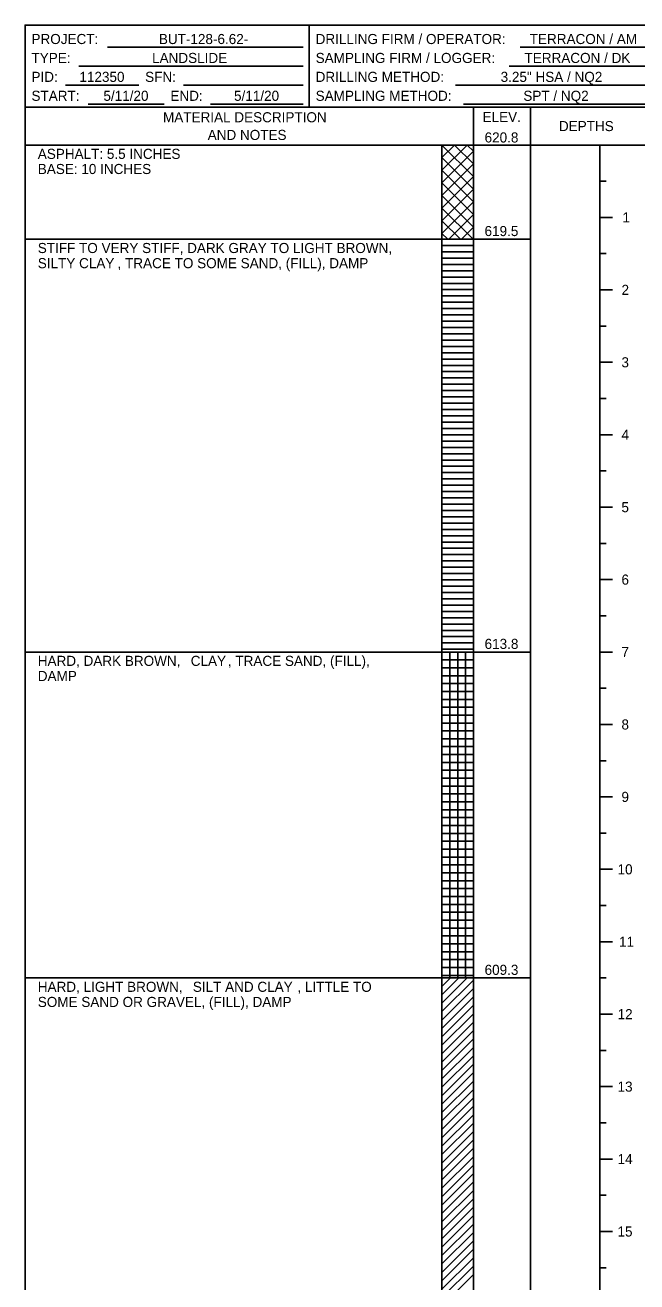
# Model space of a CAD drawing. Extents: x 0 to 0.83, y -0.65 to 1.27.
# Drawn here: x 0 to 0.404, y 0.445 to 1.275 of the extents above; entities that cross this region are included whole.
import ezdxf

# ---------------------------------------------------------------- set-up
doc = ezdxf.new("R2010")
doc.units = 0

msp = doc.modelspace()

# ---------------------------------------------------------------- linework, layer by layer
msp.add_lwpolyline([(0, 0), (0.83333, 0), (0.83333, 1.275), (0, 1.275)], close=True)
msp.add_lwpolyline([(0, 0), (0.83333, 0), (0.83333, 1.275), (0, 1.275)], close=True)
msp.add_lwpolyline([(0, 0), (0.83333, 0), (0.83333, 1.275), (0, 1.275)], close=True)
msp.add_lwpolyline([(0, 0), (0.83333, 0), (0.83333, 1.275), (0, 1.275)], close=True)
msp.add_lwpolyline([(0, 0), (0.83333, 0), (0.83333, 1.275), (0, 1.275)], close=True)
for points in [[(0.1875, 1.22083), (0.1875, 1.275)], [(0.05444, 1.26041), (0.18333, 1.26041)], [(0.32667, 1.26041), (0.4125, 1.26041)], [(0.03542, 1.24791), (0.18333, 1.24791)], [(0.31944, 1.24791), (0.4125, 1.24791)], [(0.02653, 1.23541), (0.075, 1.23541)], [(0.10458, 1.23541), (0.18333, 1.23541)], [(0.28403, 1.23541), (0.4125, 1.23541)], [(0, 1.22083), (0.83333, 1.22083)], [(0, 1.22083), (0.83333, 1.22083)], [(0, 1.22083), (0.83333, 1.22083)], [(0, 1.22083), (0.83333, 1.22083)], [(0, 1.22083), (0.83333, 1.22083)], [(0.04153, 1.22291), (0.09167, 1.22291)], [(0.12222, 1.22291), (0.18333, 1.22291)], [(0.2893, 1.22291), (0.4125, 1.22291)], [(0.29583, 1.22083), (0.29583, -0.64575)], [(0.29583, 1.22083), (0.29583, -0.64575)], [(0.33333, 1.22083), (0.33333, -0.64575)], [(0.33333, 1.22083), (0.33333, -0.64575)], [(0, 1.19583), (0.83333, 1.19583)], [(0, 1.19583), (0.83333, 1.19583)], [(0, 1.19583), (0.83333, 1.19583)], [(0, 1.19583), (0.83333, 1.19583)], [(0, 1.19583), (0.83333, 1.19583)], [(0.275, 1.19583), (0.29583, 1.175)], [(0.275, 1.1875), (0.28333, 1.19583)], [(0.275, 1.17916), (0.29167, 1.19583)], [(0.275, 1.19583), (0.275, 1.13365)], [(0.275, 1.19583), (0.275, -0.64575)], [(0.28333, 1.19583), (0.29583, 1.18333)], [(0.29167, 1.19583), (0.29583, 1.19166)], [(0.29583, 1.19583), (0.33333, 1.19583)], [(0.37917, 1.19583), (0.37917, -0.64575)], [(0.275, 1.17083), (0.29583, 1.19166)], [(0.275, 1.1875), (0.29583, 1.16666)], [(0.275, 1.1625), (0.29583, 1.18333)], [(0.275, 1.17916), (0.29583, 1.15833)], [(0.275, 1.15416), (0.29583, 1.175)], [(0.275, 1.17083), (0.29583, 1.15)], [(0.37917, 1.17191), (0.38333, 1.17191)], [(0.275, 1.14583), (0.29583, 1.16666)], [(0.275, 1.1625), (0.29583, 1.14166)], [(0.275, 1.1375), (0.29583, 1.15833)], [(0.275, 1.15416), (0.29552, 1.13365)], [(0.275, 1.14583), (0.28718, 1.13365)], [(0.27948, 1.13365), (0.29583, 1.15)], [(0.37917, 1.148), (0.3875, 1.148)], [(0.37917, 1.148), (0.38333, 1.148)], [(0.275, 1.1375), (0.27885, 1.13365)], [(0.28782, 1.13365), (0.29583, 1.14166)], [(0, 1.13365), (0.275, 1.13365)], [(0.275, 1.13365), (0.29583, 1.13365)], [(0.275, 1.13365), (0.29583, 1.13365)], [(0.275, 1.13365), (0.275, 0.861)], [(0.275, 1.12948), (0.29583, 1.12948)], [(0.29583, 1.13365), (0.33333, 1.13365)], [(0.275, 1.12531), (0.29583, 1.12531)], [(0.275, 1.12115), (0.29583, 1.12115)], [(0.37917, 1.12408), (0.38333, 1.12408)], [(0.275, 1.11698), (0.29583, 1.11698)], [(0.275, 1.11281), (0.29583, 1.11281)], [(0.275, 1.10865), (0.29583, 1.10865)], [(0.275, 1.10448), (0.29583, 1.10448)], [(0.275, 1.10031), (0.29583, 1.10031)], [(0.275, 1.09615), (0.29583, 1.09615)], [(0.37917, 1.10016), (0.3875, 1.10016)], [(0.37917, 1.10016), (0.38333, 1.10016)], [(0.275, 1.09198), (0.29583, 1.09198)], [(0.275, 1.08781), (0.29583, 1.08781)], [(0.275, 1.08365), (0.29583, 1.08365)], [(0.275, 1.07948), (0.29583, 1.07948)], [(0.275, 1.07531), (0.29583, 1.07531)], [(0.275, 1.07115), (0.29583, 1.07115)], [(0.37917, 1.07625), (0.38333, 1.07625)], [(0.275, 1.06698), (0.29583, 1.06698)], [(0.275, 1.06281), (0.29583, 1.06281)], [(0.275, 1.05865), (0.29583, 1.05865)], [(0.275, 1.05448), (0.29583, 1.05448)], [(0.275, 1.05031), (0.29583, 1.05031)], [(0.275, 1.04615), (0.29583, 1.04615)], [(0.37917, 1.05233), (0.3875, 1.05233)], [(0.37917, 1.05233), (0.38333, 1.05233)], [(0.275, 1.04198), (0.29583, 1.04198)], [(0.275, 1.03781), (0.29583, 1.03781)], [(0.275, 1.03365), (0.29583, 1.03365)], [(0.275, 1.02948), (0.29583, 1.02948)], [(0.275, 1.02531), (0.29583, 1.02531)], [(0.275, 1.02115), (0.29583, 1.02115)], [(0.37917, 1.02841), (0.38333, 1.02841)], [(0.275, 1.01698), (0.29583, 1.01698)], [(0.275, 1.01281), (0.29583, 1.01281)], [(0.275, 1.00865), (0.29583, 1.00865)], [(0.275, 1.00448), (0.29583, 1.00448)], [(0.37917, 1.0045), (0.3875, 1.0045)], [(0.37917, 1.0045), (0.38333, 1.0045)], [(0.275, 1.00031), (0.29583, 1.00031)], [(0.275, 0.99615), (0.29583, 0.99615)], [(0.275, 0.99198), (0.29583, 0.99198)], [(0.275, 0.98781), (0.29583, 0.98781)], [(0.275, 0.98365), (0.29583, 0.98365)], [(0.275, 0.97948), (0.29583, 0.97948)], [(0.37917, 0.98058), (0.38333, 0.98058)], [(0.275, 0.97531), (0.29583, 0.97531)], [(0.275, 0.97115), (0.29583, 0.97115)], [(0.275, 0.96698), (0.29583, 0.96698)], [(0.275, 0.96281), (0.29583, 0.96281)], [(0.275, 0.95865), (0.29583, 0.95865)], [(0.275, 0.95448), (0.29583, 0.95448)], [(0.37917, 0.95666), (0.3875, 0.95666)], [(0.37917, 0.95666), (0.38333, 0.95666)], [(0.275, 0.95031), (0.29583, 0.95031)], [(0.275, 0.94615), (0.29583, 0.94615)], [(0.275, 0.94198), (0.29583, 0.94198)], [(0.275, 0.93781), (0.29583, 0.93781)], [(0.275, 0.93365), (0.29583, 0.93365)], [(0.37917, 0.93275), (0.38333, 0.93275)], [(0.275, 0.92948), (0.29583, 0.92948)], [(0.275, 0.92531), (0.29583, 0.92531)], [(0.275, 0.92115), (0.29583, 0.92115)], [(0.275, 0.91698), (0.29583, 0.91698)], [(0.275, 0.91281), (0.29583, 0.91281)], [(0.275, 0.90865), (0.29583, 0.90865)], [(0.37917, 0.90883), (0.3875, 0.90883)], [(0.37917, 0.90883), (0.38333, 0.90883)], [(0.275, 0.90448), (0.29583, 0.90448)], [(0.275, 0.90031), (0.29583, 0.90031)], [(0.275, 0.89615), (0.29583, 0.89615)], [(0.275, 0.89198), (0.29583, 0.89198)], [(0.275, 0.88781), (0.29583, 0.88781)], [(0.275, 0.88365), (0.29583, 0.88365)], [(0.37917, 0.88491), (0.38333, 0.88491)], [(0.275, 0.87948), (0.29583, 0.87948)], [(0.275, 0.87531), (0.29583, 0.87531)], [(0.275, 0.87115), (0.29583, 0.87115)], [(0.275, 0.86698), (0.29583, 0.86698)], [(0, 0.861), (0.275, 0.861)], [(0.275, 0.86281), (0.29583, 0.86281)], [(0.275, 0.861), (0.29583, 0.861)], [(0.275, 0.861), (0.29583, 0.861)], [(0.275, 0.64575), (0.275, 0.861)], [(0.275, 0.861), (0.275, 0.64575)], [(0.275, 0.85579), (0.29583, 0.85579)], [(0.28021, 0.64575), (0.28021, 0.861)], [(0.28542, 0.64575), (0.28542, 0.861)], [(0.29062, 0.64575), (0.29062, 0.861)], [(0.29583, 0.64575), (0.29583, 0.861)], [(0.29583, 0.861), (0.33333, 0.861)], [(0.37917, 0.861), (0.3875, 0.861)], [(0.37917, 0.861), (0.38333, 0.861)], [(0.275, 0.85058), (0.29583, 0.85058)], [(0.275, 0.84537), (0.29583, 0.84537)], [(0.275, 0.84016), (0.29583, 0.84016)], [(0.275, 0.83496), (0.29583, 0.83496)], [(0.37917, 0.83708), (0.38333, 0.83708)], [(0.275, 0.82975), (0.29583, 0.82975)], [(0.275, 0.82454), (0.29583, 0.82454)], [(0.275, 0.81933), (0.29583, 0.81933)], [(0.275, 0.81412), (0.29583, 0.81412)], [(0.275, 0.80892), (0.29583, 0.80892)], [(0.37917, 0.81317), (0.3875, 0.81317)], [(0.37917, 0.81317), (0.38333, 0.81317)], [(0.275, 0.80371), (0.29583, 0.80371)], [(0.275, 0.7985), (0.29583, 0.7985)], [(0.275, 0.79329), (0.29583, 0.79329)], [(0.37917, 0.78925), (0.38333, 0.78925)], [(0.275, 0.78808), (0.29583, 0.78808)], [(0.275, 0.78287), (0.29583, 0.78287)], [(0.275, 0.77767), (0.29583, 0.77767)], [(0.275, 0.77246), (0.29583, 0.77246)], [(0.275, 0.76725), (0.29583, 0.76725)], [(0.37917, 0.76533), (0.3875, 0.76533)], [(0.37917, 0.76533), (0.38333, 0.76533)], [(0.275, 0.76204), (0.29583, 0.76204)], [(0.275, 0.75683), (0.29583, 0.75683)], [(0.275, 0.75162), (0.29583, 0.75162)], [(0.275, 0.74642), (0.29583, 0.74642)], [(0.275, 0.74121), (0.29583, 0.74121)], [(0.37917, 0.74142), (0.38333, 0.74142)], [(0.275, 0.736), (0.29583, 0.736)], [(0.275, 0.73079), (0.29583, 0.73079)], [(0.275, 0.72558), (0.29583, 0.72558)], [(0.275, 0.72037), (0.29583, 0.72037)], [(0.275, 0.71517), (0.29583, 0.71517)], [(0.37917, 0.7175), (0.3875, 0.7175)], [(0.37917, 0.7175), (0.38333, 0.7175)], [(0.275, 0.70996), (0.29583, 0.70996)], [(0.275, 0.70475), (0.29583, 0.70475)], [(0.275, 0.69954), (0.29583, 0.69954)], [(0.275, 0.69433), (0.29583, 0.69433)], [(0.275, 0.68912), (0.29583, 0.68912)], [(0.37917, 0.69358), (0.38333, 0.69358)], [(0.275, 0.68392), (0.29583, 0.68392)], [(0.275, 0.67871), (0.29583, 0.67871)], [(0.275, 0.6735), (0.29583, 0.6735)], [(0.275, 0.66829), (0.29583, 0.66829)], [(0.37917, 0.66967), (0.3875, 0.66967)], [(0.37917, 0.66967), (0.38333, 0.66967)], [(0.275, 0.66308), (0.29583, 0.66308)], [(0.275, 0.65787), (0.29583, 0.65787)], [(0.275, 0.65267), (0.29583, 0.65267)], [(0.275, 0.64746), (0.29583, 0.64746)], [(0, 0.64575), (0.275, 0.64575)], [(0.275, 0.64575), (0.29583, 0.64575)], [(0.275, 0.64019), (0.28055, 0.64575)], [(0.275, 0.63464), (0.28611, 0.64575)], [(0.275, 0.62908), (0.29167, 0.64575)], [(0.275, 0.64575), (0.275, 0.35875)], [(0.275, 0.62353), (0.29583, 0.64436)], [(0.29583, 0.64575), (0.33333, 0.64575)], [(0.37917, 0.64575), (0.38333, 0.64575)], [(0.275, 0.61797), (0.29583, 0.6388)], [(0.275, 0.61242), (0.29583, 0.63325)], [(0.275, 0.60686), (0.29583, 0.62769)], [(0.275, 0.6013), (0.29583, 0.62214)], [(0.275, 0.59575), (0.29583, 0.61658)], [(0.37917, 0.62183), (0.3875, 0.62183)], [(0.37917, 0.62183), (0.38333, 0.62183)], [(0.275, 0.59019), (0.29583, 0.61103)], [(0.275, 0.58464), (0.29583, 0.60547)], [(0.275, 0.57908), (0.29583, 0.59992)], [(0.37917, 0.59792), (0.38333, 0.59792)], [(0.275, 0.57353), (0.29583, 0.59436)], [(0.275, 0.56797), (0.29583, 0.5888)], [(0.275, 0.56242), (0.29583, 0.58325)], [(0.275, 0.55686), (0.29583, 0.57769)], [(0.37917, 0.574), (0.3875, 0.574)], [(0.37917, 0.574), (0.38333, 0.574)], [(0.275, 0.5513), (0.29583, 0.57214)], [(0.275, 0.54575), (0.29583, 0.56658)], [(0.275, 0.54019), (0.29583, 0.56103)], [(0.275, 0.53464), (0.29583, 0.55547)], [(0.275, 0.52908), (0.29583, 0.54992)], [(0.37917, 0.55008), (0.38333, 0.55008)], [(0.275, 0.52353), (0.29583, 0.54436)], [(0.275, 0.51797), (0.29583, 0.5388)], [(0.275, 0.51242), (0.29583, 0.53325)], [(0.275, 0.50686), (0.29583, 0.52769)], [(0.37917, 0.52617), (0.3875, 0.52617)], [(0.37917, 0.52617), (0.38333, 0.52617)], [(0.275, 0.5013), (0.29583, 0.52214)], [(0.275, 0.49575), (0.29583, 0.51658)], [(0.275, 0.49019), (0.29583, 0.51103)], [(0.275, 0.48464), (0.29583, 0.50547)], [(0.275, 0.47908), (0.29583, 0.49992)], [(0.37917, 0.50225), (0.38333, 0.50225)], [(0.275, 0.47353), (0.29583, 0.49436)], [(0.275, 0.46797), (0.29583, 0.4888)], [(0.275, 0.46242), (0.29583, 0.48325)], [(0.275, 0.45686), (0.29583, 0.47769)], [(0.37917, 0.47833), (0.3875, 0.47833)], [(0.37917, 0.47833), (0.38333, 0.47833)], [(0.275, 0.4513), (0.29583, 0.47214)], [(0.275, 0.44575), (0.29583, 0.46658)], [(0.275, 0.44019), (0.29583, 0.46103)], [(0.275, 0.43464), (0.29583, 0.45547)], [(0.275, 0.42908), (0.29583, 0.44992)], [(0.37917, 0.45442), (0.38333, 0.45442)]]:
    msp.add_lwpolyline(points)

# ---------------------------------------------------------------- texts
for s, height, p in [('PROJECT:', 0.006667, (0.00417, 1.2625)), ('BUT-128-6.62-', 0.0066667, (0.08824, 1.2625)), ('DRILLING FIRM / OPERATOR:', 0.0066667, (0.19167, 1.2625)), ('TERRACON / AM', 0.0066667, (0.33293, 1.2625)), ('TYPE:', 0.006667, (0.00417, 1.25)), ('LANDSLIDE', 0.006667, (0.08374, 1.25)), ('SAMPLING FIRM / LOGGER:', 0.0066667, (0.19167, 1.25)), ('TERRACON / DK', 0.0066667, (0.32949, 1.25)), ('PID:', 0.006667, (0.00417, 1.2375)), ('112350', 0.006667, (0.0358, 1.2375)), ('SFN:', 0.006667, (0.07917, 1.2375)), ('DRILLING METHOD:', 0.0066667, (0.19167, 1.2375)), ('3.25" HSA / NQ2', 0.0066667, (0.31373, 1.2375)), ('START:', 0.006667, (0.00417, 1.225)), ('5/11/20', 0.006667, (0.05164, 1.225)), ('END:', 0.006667, (0.09583, 1.225)), ('5/11/20', 0.006667, (0.13782, 1.225)), ('SAMPLING METHOD:', 0.0066667, (0.19167, 1.225)), ('SPT / NQ2', 0.006667, (0.32872, 1.225)), ('MATERIAL DESCRIPTION', 0.0066667, (0.09097, 1.21083)), ('ELEV.', 0.006667, (0.30179, 1.21104)), ('DEPTHS', 0.006667, (0.35218, 1.205)), ('AND NOTES', 0.006667, (0.12044, 1.19916)), ('620.8', 0.006667, (0.30314, 1.1975)), ('ASPHALT: 5.5 INCHES', 0.0066667, (0.00833, 1.18666)), ('BASE: 10 INCHES', 0.0066667, (0.00833, 1.17666)), ('1', 0.00667, (0.3941, 1.14466)), ('619.5', 0.006667, (0.30312, 1.13569)), ('STIFF TO VERY STIFF, DARK GRAY TO LIGHT BROWN,', 0.0066667, (0.00833, 1.12448)), ('SILTY CLAY', 0.006667, (0.00833, 1.11448)), (', TRACE TO SOME SAND, (FILL), DAMP', 0.0066667, (0.06097, 1.11448)), ('2', 0.00667, (0.39349, 1.09683)), ('3', 0.00667, (0.39345, 1.049)), ('4', 0.00667, (0.39347, 1.00116)), ('5', 0.00667, (0.39343, 0.95333)), ('6', 0.00667, (0.39345, 0.9055)), ('613.8', 0.006667, (0.30314, 0.86304)), ('7', 0.00667, (0.39345, 0.85766)), ('HARD, DARK BROWN, ', 0.0066667, (0.00833, 0.85183)), ('CLAY', 0.006667, (0.10925, 0.85183)), (', TRACE SAND, (FILL),', 0.0066667, (0.13376, 0.85183)), ('DAMP', 0.006667, (0.00833, 0.84183)), ('8', 0.00667, (0.39345, 0.80983)), ('9', 0.00667, (0.39345, 0.762)), ('10', 0.006667, (0.39088, 0.71417)), ('11', 0.006667, (0.39186, 0.66633)), ('609.3', 0.006667, (0.30314, 0.64779)), ('HARD, LIGHT BROWN, ', 0.0066667, (0.00833, 0.63658)), ('SILT AND CLAY', 0.0066667, (0.11063, 0.63658)), (', LITTLE TO', 0.0066667, (0.17964, 0.63658)), ('SOME SAND OR GRAVEL, (FILL), DAMP', 0.0066667, (0.00833, 0.62658)), ('12', 0.006667, (0.3909, 0.6185)), ('13', 0.006667, (0.39087, 0.57067)), ('14', 0.006667, (0.39088, 0.52283)), ('15', 0.006667, (0.39084, 0.475))]:
    msp.add_text(s, height=height).set_placement(p)

doc.saveas('drawing.dxf')
